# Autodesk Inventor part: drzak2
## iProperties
Shininess: 64.0
Length Units: 11269
Angle Units: 11279
Time Units: 11290
Mass Units: 11283
Length Display Precision: 3
Angle Display Precision: 2
Compacted: True
+MSCFeatProtocols1+FeatNameP00080516064119399: HCNTB_MM1
+MSCFeatProtocols2+ProtocolIDP00080516064119399: P00080516064119399
+MSCFeatProtocols3+ProtocolP00080516064119399: P00080516064119399<@PID>[View]<@EL>View=MODEL_HOLE_FM<@EL>Description=Feature<@EL>VISIBLED=1<@EL>Data=(setq _data (list "M5" "5.30" "In drawing" "4.50" "15.00" 
+MSCFeatProtocols4+FeatNameP00080516064657915: HCNTB_MM2
+MSCFeatProtocols5+ProtocolIDP00080516064657915: P00080516064657915
+MSCFeatProtocols6+ProtocolP00080516064657915: P00080516064657915<@PID>[Version]<@EL>Version=2.2<@EL>[Notes]<@EL>Line0=<@EL>LineCount=1<@EL>[View]<@EL>Data=(setq _data (list "M5" "5.30" "29" "5.70" "10.00" "
+MSCFeatProtocols7+FeatNameP00080518095240078: HCNTB_MM3
+MSCFeatProtocols8+ProtocolIDP00080518095240078: P00080518095240078
+MSCFeatProtocols9+ProtocolP00080518095240078: P00080518095240078<@PID>[View]<@EL>View=MODEL_HOLE_FM<@EL>Description=Feature<@EL>VISIBLED=1<@EL>Data=(setq _data (list "M5" "5.30" "In drawing" "4.50" "15.00" 
+MSCFeatProtocols10+FeatNameP00080518101630515: HCNTB_MM4
+MSCFeatProtocols11+ProtocolIDP00080518101630515: P00080518101630515
+MSCFeatProtocols12+ProtocolP00080518101630515: P00080518101630515<@PID>[Version]<@EL>Version=2.2<@EL>[Data]<@EL>d1=10{mm<@EL>L=30{mm<@EL>t=7.2{mm<@EL>d=5.3{mm<@EL>Ds=5{mm<@EL>[BaseView]<@EL>RefMenu=#SPIDATA|
+MSCProtocol1+ProtocolID: P00080516065926061
+MSCProtocol2+Protocol: P00080516065926061<@PID>[Object]<@EL>CADDescription=drzak2.ipt<@EL>[GroupMan]<@EL>UseUserDescription=1<@EL>UserDescription=drzak2.ipt<@EL>[ACAD]<@EL>SmartPart=1
Part Number: drzak2
Document SubType Name: Modeling
Created: 2008-05
Designer: Admin
Manufacturer: Standard
Standards Organization: Custom
Density: 0.0
Volumn: 0.0
Area: 0.0
PropertySet Name: Model Information
Control State: 0
Master: False
Checked Out: False
Author: Admin
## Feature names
1. Extrusion1
2. Extrusion2
3. Hole2
4. Chamfer1
5. Chamfer2
6. Hole3
7. Hole4
